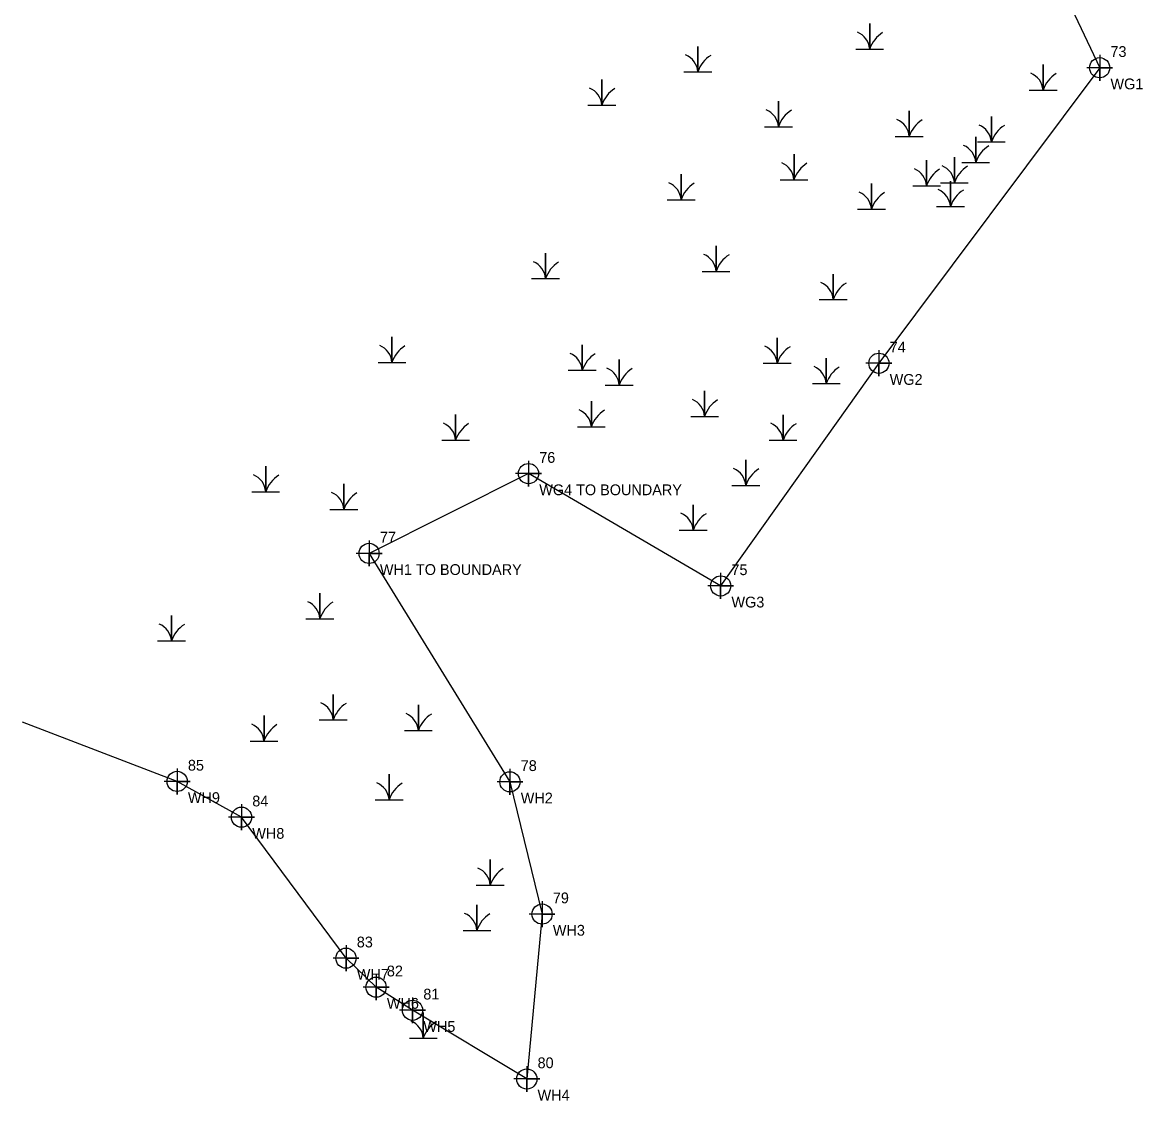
# Model space of a CAD drawing. Extents: x 2189822 to 2190837, y 387253 to 388663.
# Drawn here: x 2189822.3 to 2190081.9, y 387438.8 to 387688.6 of the extents above; entities that cross this region are included whole.
import ezdxf

# ---------------------------------------------------------------- set-up
doc = ezdxf.new("R2010")
doc.units = 0
for name, color, linetype in [('COGO Default Chain', 7, 'Continuous'), ('DTM Contours Major', 7, 'Continuous'), ('DTM Contours Minor', 7, 'Continuous'), ('Exist DTM Breakline Cogo Elevation', 7, 'Continuous'), ('Exist DTM Breakline Cogo Number', 7, 'Continuous')]:
    doc.layers.add(name, color=color, linetype=linetype)

msp = doc.modelspace()

# ---------------------------------------------------------------- linework, layer by layer
at = {"layer": 'DTM Contours Major'}
for points in [[(2190072, 387681.13), (2190072, 387675.13), (2190072, 387678.13), (2190075, 387678.13), (2190069, 387678.13)], [(2190020.83, 387612.65), (2190020.83, 387606.65), (2190020.83, 387609.65), (2190023.83, 387609.65), (2190017.83, 387609.65)], [(2189939.6, 387587.08), (2189939.6, 387581.08), (2189939.6, 387584.08), (2189942.6, 387584.08), (2189936.6, 387584.08)], [(2189902.66, 387568.6), (2189902.66, 387562.6), (2189902.66, 387565.6), (2189905.66, 387565.6), (2189899.66, 387565.6)], [(2189984.15, 387561.06), (2189984.15, 387555.06), (2189984.15, 387558.06), (2189987.15, 387558.06), (2189981.15, 387558.06)], [(2189858.16, 387515.76), (2189858.16, 387509.76), (2189858.16, 387512.76), (2189861.16, 387512.76), (2189855.16, 387512.76)], [(2189935.31, 387515.67), (2189935.31, 387509.67), (2189935.31, 387512.67), (2189938.31, 387512.67), (2189932.31, 387512.67)], [(2189873.08, 387507.47), (2189873.08, 387501.47), (2189873.08, 387504.47), (2189876.08, 387504.47), (2189870.08, 387504.47)], [(2189942.75, 387485.02), (2189942.75, 387479.02), (2189942.75, 387482.02), (2189945.75, 387482.02), (2189939.75, 387482.02)], [(2189897.31, 387474.8), (2189897.31, 387468.8), (2189897.31, 387471.8), (2189900.31, 387471.8), (2189894.31, 387471.8)], [(2189904.28, 387468.08), (2189904.28, 387462.08), (2189904.28, 387465.08), (2189907.28, 387465.08), (2189901.28, 387465.08)], [(2189912.73, 387462.73), (2189912.73, 387456.73), (2189912.73, 387459.73), (2189915.73, 387459.73), (2189909.73, 387459.73)], [(2189939.21, 387446.81), (2189939.21, 387440.81), (2189939.21, 387443.81), (2189942.21, 387443.81), (2189936.21, 387443.81)]]:
    msp.add_lwpolyline(points, dxfattribs=at)
for centre in [(2190072, 387678.13), (2190020.83, 387609.65), (2189939.6, 387584.08), (2189902.66, 387565.6), (2189984.15, 387558.06), (2189858.16, 387512.76), (2189935.31, 387512.67), (2189873.08, 387504.47), (2189942.75, 387482.02), (2189897.31, 387471.8), (2189904.28, 387465.08), (2189912.73, 387459.73), (2189939.21, 387443.81)]:
    msp.add_circle(centre, 2.34, dxfattribs=at)
at = {"layer": 'Exist DTM Breakline Cogo Elevation'}
for p, q in [((2190018.69, 387685.13), (2190018.69, 387685.13)), ((2189978.86, 387679.84), (2189978.86, 387679.84)), ((2190058.88, 387675.6), (2190058.88, 387675.6)), ((2189956.61, 387672.15), (2189956.61, 387672.15)), ((2189997.54, 387667.14), (2189997.54, 387667.14)), ((2190027.85, 387664.86), (2190027.85, 387664.86)), ((2190046.89, 387663.61), (2190046.89, 387663.61)), ((2190043.28, 387658.87), (2190043.28, 387658.87)), ((2190001.15, 387654.84), (2190001.15, 387654.84)), ((2190031.88, 387653.46), (2190031.88, 387653.46)), ((2190038.33, 387654.15), (2190038.33, 387654.15)), ((2189974.98, 387650.21), (2189974.98, 387650.21)), ((2190037.41, 387648.62), (2190037.41, 387648.62)), ((2190019.1, 387648.05), (2190019.1, 387648.05)), ((2189983.09, 387633.63), (2189983.09, 387633.63)), ((2189943.57, 387631.93), (2189943.57, 387631.93)), ((2190010.24, 387627.08), (2190010.24, 387627.08)), ((2189907.96, 387612.53), (2189907.96, 387612.53)), ((2189997.23, 387612.34), (2189997.23, 387612.34)), ((2189952.07, 387610.7), (2189952.07, 387610.7)), ((2189960.63, 387607.27), (2189960.63, 387607.27)), ((2190008.63, 387607.62), (2190008.63, 387607.62)), ((2189980.43, 387600.01), (2189980.43, 387600.01)), ((2189954.18, 387597.6), (2189954.18, 387597.6)), ((2189922.72, 387594.51), (2189922.72, 387594.51)), ((2189998.61, 387594.49), (2189998.61, 387594.49)), ((2189989.98, 387584), (2189989.98, 387584)), ((2189878.7, 387582.55), (2189878.7, 387582.55)), ((2189896.81, 387578.46), (2189896.81, 387578.46)), ((2189977.78, 387573.64), (2189977.78, 387573.64)), ((2189891.26, 387553.15), (2189891.26, 387553.15)), ((2189856.85, 387547.98), (2189856.85, 387547.98)), ((2189894.34, 387529.69), (2189894.34, 387529.69)), ((2189914.08, 387527.22), (2189914.08, 387527.22)), ((2189878.3, 387524.75), (2189878.3, 387524.75)), ((2189907.29, 387511.17), (2189907.29, 387511.17)), ((2189930.74, 387491.42), (2189930.74, 387491.42)), ((2189927.65, 387480.92), (2189927.65, 387480.92)), ((2189915.23, 387455.98), (2189915.23, 387455.98))]:
    msp.add_line(p, q, dxfattribs=at)
for points in [[(2190015.47, 387682.45), (2190018.69, 387682.45), (2190018.69, 387688.37), (2190018.69, 387682.45), (2190021.92, 387682.45)], [(2189975.63, 387677.16), (2189978.86, 387677.16), (2189978.86, 387683.08), (2189978.86, 387677.16), (2189982.08, 387677.16)], [(2190055.66, 387672.93), (2190058.88, 387672.93), (2190058.88, 387678.85), (2190058.88, 387672.93), (2190062.11, 387672.93)], [(2189953.39, 387669.47), (2189956.61, 387669.47), (2189956.61, 387675.39), (2189956.61, 387669.47), (2189959.84, 387669.47)], [(2189994.32, 387664.46), (2189997.54, 387664.46), (2189997.54, 387670.38), (2189997.54, 387664.46), (2190000.77, 387664.46)], [(2190024.63, 387662.19), (2190027.85, 387662.19), (2190027.85, 387668.11), (2190027.85, 387662.19), (2190031.08, 387662.19)], [(2190043.67, 387660.94), (2190046.9, 387660.94), (2190046.9, 387666.85), (2190046.9, 387660.94), (2190050.12, 387660.94)], [(2190040.05, 387656.2), (2190043.28, 387656.2), (2190043.28, 387662.12), (2190043.28, 387656.2), (2190046.5, 387656.2)], [(2189997.92, 387652.17), (2190001.15, 387652.17), (2190001.15, 387658.09), (2190001.15, 387652.17), (2190004.37, 387652.17)], [(2190028.66, 387650.79), (2190031.88, 387650.79), (2190031.88, 387656.7), (2190031.88, 387650.79), (2190035.11, 387650.79)], [(2190035.1, 387651.48), (2190038.33, 387651.48), (2190038.33, 387657.39), (2190038.33, 387651.48), (2190041.55, 387651.48)], [(2189971.75, 387647.53), (2189974.98, 387647.53), (2189974.98, 387653.45), (2189974.98, 387647.53), (2189978.21, 387647.53)], [(2190015.88, 387645.37), (2190019.1, 387645.37), (2190019.1, 387651.29), (2190019.1, 387645.37), (2190022.33, 387645.37)], [(2190034.18, 387645.95), (2190037.41, 387645.95), (2190037.41, 387651.87), (2190037.41, 387645.95), (2190040.63, 387645.95)], [(2189979.86, 387630.95), (2189983.09, 387630.95), (2189983.09, 387636.87), (2189983.09, 387630.95), (2189986.31, 387630.95)], [(2189940.34, 387629.26), (2189943.57, 387629.26), (2189943.57, 387635.18), (2189943.57, 387629.26), (2189946.79, 387629.26)], [(2190007.01, 387624.41), (2190010.24, 387624.41), (2190010.24, 387630.33), (2190010.24, 387624.41), (2190013.47, 387624.41)], [(2189904.74, 387609.86), (2189907.96, 387609.86), (2189907.96, 387615.77), (2189907.96, 387609.86), (2189911.19, 387609.86)], [(2189994.01, 387609.67), (2189997.23, 387609.67), (2189997.23, 387615.58), (2189997.23, 387609.67), (2190000.46, 387609.67)], [(2189948.84, 387608.02), (2189952.07, 387608.02), (2189952.07, 387613.94), (2189952.07, 387608.02), (2189955.29, 387608.02)], [(2189957.4, 387604.6), (2189960.63, 387604.6), (2189960.63, 387610.51), (2189960.63, 387604.6), (2189963.85, 387604.6)], [(2190005.4, 387604.94), (2190008.63, 387604.94), (2190008.63, 387610.86), (2190008.63, 387604.94), (2190011.85, 387604.94)], [(2189977.2, 387597.34), (2189980.43, 387597.34), (2189980.43, 387603.26), (2189980.43, 387597.34), (2189983.65, 387597.34)], [(2189950.96, 387594.92), (2189954.18, 387594.92), (2189954.18, 387600.84), (2189954.18, 387594.92), (2189957.41, 387594.92)], [(2189919.49, 387591.83), (2189922.72, 387591.83), (2189922.72, 387597.75), (2189922.72, 387591.83), (2189925.94, 387591.83)], [(2189995.39, 387591.81), (2189998.61, 387591.81), (2189998.61, 387597.73), (2189998.61, 387591.81), (2190001.84, 387591.81)], [(2189986.76, 387581.33), (2189989.98, 387581.33), (2189989.98, 387587.25), (2189989.98, 387581.33), (2189993.21, 387581.33)], [(2189875.48, 387579.87), (2189878.7, 387579.87), (2189878.7, 387585.79), (2189878.7, 387579.87), (2189881.93, 387579.87)], [(2189893.58, 387575.78), (2189896.81, 387575.78), (2189896.81, 387581.7), (2189896.81, 387575.78), (2189900.03, 387575.78)], [(2189974.55, 387570.96), (2189977.78, 387570.96), (2189977.78, 387576.88), (2189977.78, 387570.96), (2189981, 387570.96)], [(2189888.03, 387550.47), (2189891.26, 387550.47), (2189891.26, 387556.39), (2189891.26, 387550.47), (2189894.48, 387550.47)], [(2189853.62, 387545.3), (2189856.85, 387545.3), (2189856.85, 387551.22), (2189856.85, 387545.3), (2189860.07, 387545.3)], [(2189891.11, 387527.02), (2189894.34, 387527.02), (2189894.34, 387532.93), (2189894.34, 387527.02), (2189897.57, 387527.02)], [(2189910.86, 387524.55), (2189914.08, 387524.55), (2189914.08, 387530.47), (2189914.08, 387524.55), (2189917.31, 387524.55)], [(2189875.07, 387522.08), (2189878.3, 387522.08), (2189878.3, 387528), (2189878.3, 387522.08), (2189881.53, 387522.08)], [(2189904.07, 387508.5), (2189907.3, 387508.5), (2189907.3, 387514.42), (2189907.3, 387508.5), (2189910.52, 387508.5)], [(2189927.51, 387488.74), (2189930.74, 387488.74), (2189930.74, 387494.66), (2189930.74, 387488.74), (2189933.96, 387488.74)], [(2189924.43, 387478.25), (2189927.65, 387478.25), (2189927.65, 387484.17), (2189927.65, 387478.25), (2189930.88, 387478.25)], [(2189912, 387453.3), (2189915.23, 387453.3), (2189915.23, 387459.22), (2189915.23, 387453.3), (2189918.45, 387453.3)]]:
    msp.add_lwpolyline(points, dxfattribs=at)
for centre, radius, start, end in [((2190014.09, 387682.12), 4.61, 4.1403, 67.535), ((2190025.53, 387680.18), 7.21, 122.1274, 161.6222), ((2189974.26, 387676.83), 4.61, 4.1403, 67.535), ((2189985.7, 387674.89), 7.21, 122.1274, 161.6222), ((2190054.28, 387672.6), 4.61, 4.1403, 67.535), ((2190065.72, 387670.66), 7.21, 122.1274, 161.6222), ((2189952.01, 387669.14), 4.61, 4.1403, 67.535), ((2189963.45, 387667.2), 7.21, 122.1274, 161.6222), ((2189992.94, 387664.13), 4.61, 4.1403, 67.535), ((2190004.38, 387662.19), 7.21, 122.1274, 161.6222), ((2190023.25, 387661.86), 4.61, 4.1403, 67.535), ((2190034.69, 387659.92), 7.21, 122.1274, 161.6222), ((2190042.3, 387660.6), 4.61, 4.1403, 67.535), ((2190053.74, 387658.66), 7.21, 122.1274, 161.6222), ((2190038.68, 387655.87), 4.61, 4.1403, 67.535), ((2190050.12, 387653.93), 7.21, 122.1274, 161.6222), ((2189996.55, 387651.84), 4.61, 4.1403, 67.535), ((2190007.99, 387649.9), 7.21, 122.1274, 161.6222), ((2190027.28, 387650.45), 4.61, 4.1403, 67.535), ((2190038.72, 387648.51), 7.21, 122.1274, 161.6222), ((2190033.73, 387651.14), 4.61, 4.1403, 67.535), ((2190045.17, 387649.2), 7.21, 122.1274, 161.6222), ((2189970.38, 387647.2), 4.61, 4.1403, 67.535), ((2189981.82, 387645.26), 7.21, 122.1274, 161.6222), ((2190014.5, 387645.04), 4.61, 4.1403, 67.535), ((2190025.94, 387643.1), 7.21, 122.1274, 161.6222), ((2190032.81, 387645.62), 4.61, 4.1403, 67.535), ((2190044.25, 387643.68), 7.21, 122.1274, 161.6222), ((2189938.97, 387628.92), 4.61, 4.1403, 67.535), ((2189950.41, 387626.98), 7.21, 122.1274, 161.6222), ((2189978.49, 387630.62), 4.61, 4.1403, 67.535), ((2189989.93, 387628.68), 7.21, 122.1274, 161.6222), ((2190005.64, 387624.08), 4.61, 4.1403, 67.535), ((2190017.08, 387622.14), 7.21, 122.1274, 161.6222), ((2189903.36, 387609.52), 4.61, 4.1403, 67.535), ((2189914.8, 387607.58), 7.21, 122.1274, 161.6222), ((2189947.47, 387607.69), 4.61, 4.1403, 67.535), ((2189992.63, 387609.33), 4.61, 4.1403, 67.535), ((2190004.07, 387607.39), 7.21, 122.1274, 161.6222), ((2189958.91, 387605.75), 7.21, 122.1274, 161.6222), ((2189956.03, 387604.26), 4.61, 4.1403, 67.535), ((2189967.47, 387602.32), 7.21, 122.1274, 161.6222), ((2190004.03, 387604.61), 4.61, 4.1403, 67.535), ((2190015.47, 387602.67), 7.21, 122.1274, 161.6222), ((2189975.83, 387597.01), 4.61, 4.1403, 67.535), ((2189987.27, 387595.07), 7.21, 122.1274, 161.6222), ((2189949.58, 387594.59), 4.61, 4.1403, 67.535), ((2189961.02, 387592.65), 7.21, 122.1274, 161.6222), ((2189918.12, 387591.5), 4.61, 4.1403, 67.535), ((2189929.56, 387589.56), 7.21, 122.1274, 161.6222), ((2189994.01, 387591.48), 4.61, 4.1403, 67.535), ((2190005.45, 387589.54), 7.21, 122.1274, 161.6222), ((2189874.1, 387579.54), 4.61, 4.1403, 67.535), ((2189885.54, 387577.6), 7.21, 122.1274, 161.6222), ((2189985.38, 387581), 4.61, 4.1403, 67.535), ((2189996.82, 387579.06), 7.21, 122.1274, 161.6222), ((2189892.21, 387575.45), 4.61, 4.1403, 67.535), ((2189903.65, 387573.51), 7.21, 122.1274, 161.6222), ((2189973.18, 387570.63), 4.61, 4.1403, 67.535), ((2189984.62, 387568.69), 7.21, 122.1274, 161.6222), ((2189886.66, 387550.14), 4.61, 4.1403, 67.535), ((2189898.1, 387548.2), 7.21, 122.1274, 161.6222), ((2189852.25, 387544.97), 4.61, 4.1403, 67.535), ((2189863.69, 387543.03), 7.21, 122.1274, 161.6222), ((2189889.74, 387526.68), 4.61, 4.1403, 67.535), ((2189901.18, 387524.74), 7.21, 122.1274, 161.6222), ((2189909.48, 387524.21), 4.61, 4.1403, 67.535), ((2189920.92, 387522.27), 7.21, 122.1274, 161.6222), ((2189873.7, 387521.75), 4.61, 4.1403, 67.535), ((2189885.14, 387519.81), 7.21, 122.1274, 161.6222), ((2189902.7, 387508.16), 4.61, 4.1403, 67.535), ((2189914.14, 387506.22), 7.21, 122.1274, 161.6222), ((2189926.14, 387488.41), 4.61, 4.1403, 67.535), ((2189937.58, 387486.47), 7.21, 122.1274, 161.6222), ((2189923.05, 387477.92), 4.61, 4.1403, 67.535), ((2189934.49, 387475.98), 7.21, 122.1274, 161.6222), ((2189910.63, 387452.97), 4.61, 4.1403, 67.535), ((2189922.07, 387451.03), 7.21, 122.1274, 161.6222)]:
    msp.add_arc(centre, radius, start, end, dxfattribs=at)
at = {"layer": 'Exist DTM Breakline Cogo Number'}
msp.add_line((2189858.16, 387512.76), (2189822.3, 387526.46), dxfattribs=at)
for points in [[(2190029.88, 387766.97), (2190072, 387678.13)], [(2190072, 387678.13), (2190020.83, 387609.65), (2189984.15, 387558.06), (2189939.6, 387584.08), (2189902.66, 387565.6), (2189935.31, 387512.67), (2189942.75, 387482.02), (2189939.21, 387443.81), (2189912.73, 387459.73), (2189904.28, 387465.08), (2189897.31, 387471.8), (2189873.08, 387504.47), (2189858.16, 387512.76)]]:
    msp.add_lwpolyline(points, dxfattribs=at)

# ---------------------------------------------------------------- texts
at = {"layer": 'COGO Default Chain'}
for s, p in [('WG1', (2190074.5, 387673.13)), ('WG2', (2190023.33, 387604.65)), ('WG4 TO BOUNDARY', (2189942.1, 387579.08)), ('WH1 TO BOUNDARY', (2189905.16, 387560.6)), ('WG3', (2189986.65, 387553.06)), ('WH9', (2189860.66, 387507.76)), ('WH2', (2189937.81, 387507.67)), ('WH8', (2189875.58, 387499.47)), ('WH3', (2189945.25, 387477.02)), ('WH7', (2189899.81, 387466.8)), ('WH6', (2189906.78, 387460.08)), ('WH5', (2189915.23, 387454.73)), ('WH4', (2189941.71, 387438.81))]:
    msp.add_text(s, height=2.5, dxfattribs=at).set_placement(p)
at = {"layer": 'DTM Contours Minor'}
for s, p in [('73', (2190074.5, 387680.63)), ('74', (2190023.33, 387612.15)), ('76', (2189942.1, 387586.58)), ('77', (2189905.16, 387568.1)), ('75', (2189986.65, 387560.56)), ('85', (2189860.66, 387515.26)), ('78', (2189937.81, 387515.17)), ('84', (2189875.58, 387506.97)), ('79', (2189945.25, 387484.52)), ('83', (2189899.81, 387474.3)), ('82', (2189906.78, 387467.58)), ('81', (2189915.23, 387462.23)), ('80', (2189941.71, 387446.31))]:
    msp.add_text(s, height=2.5, dxfattribs=at).set_placement(p)

doc.saveas('drawing.dxf')
